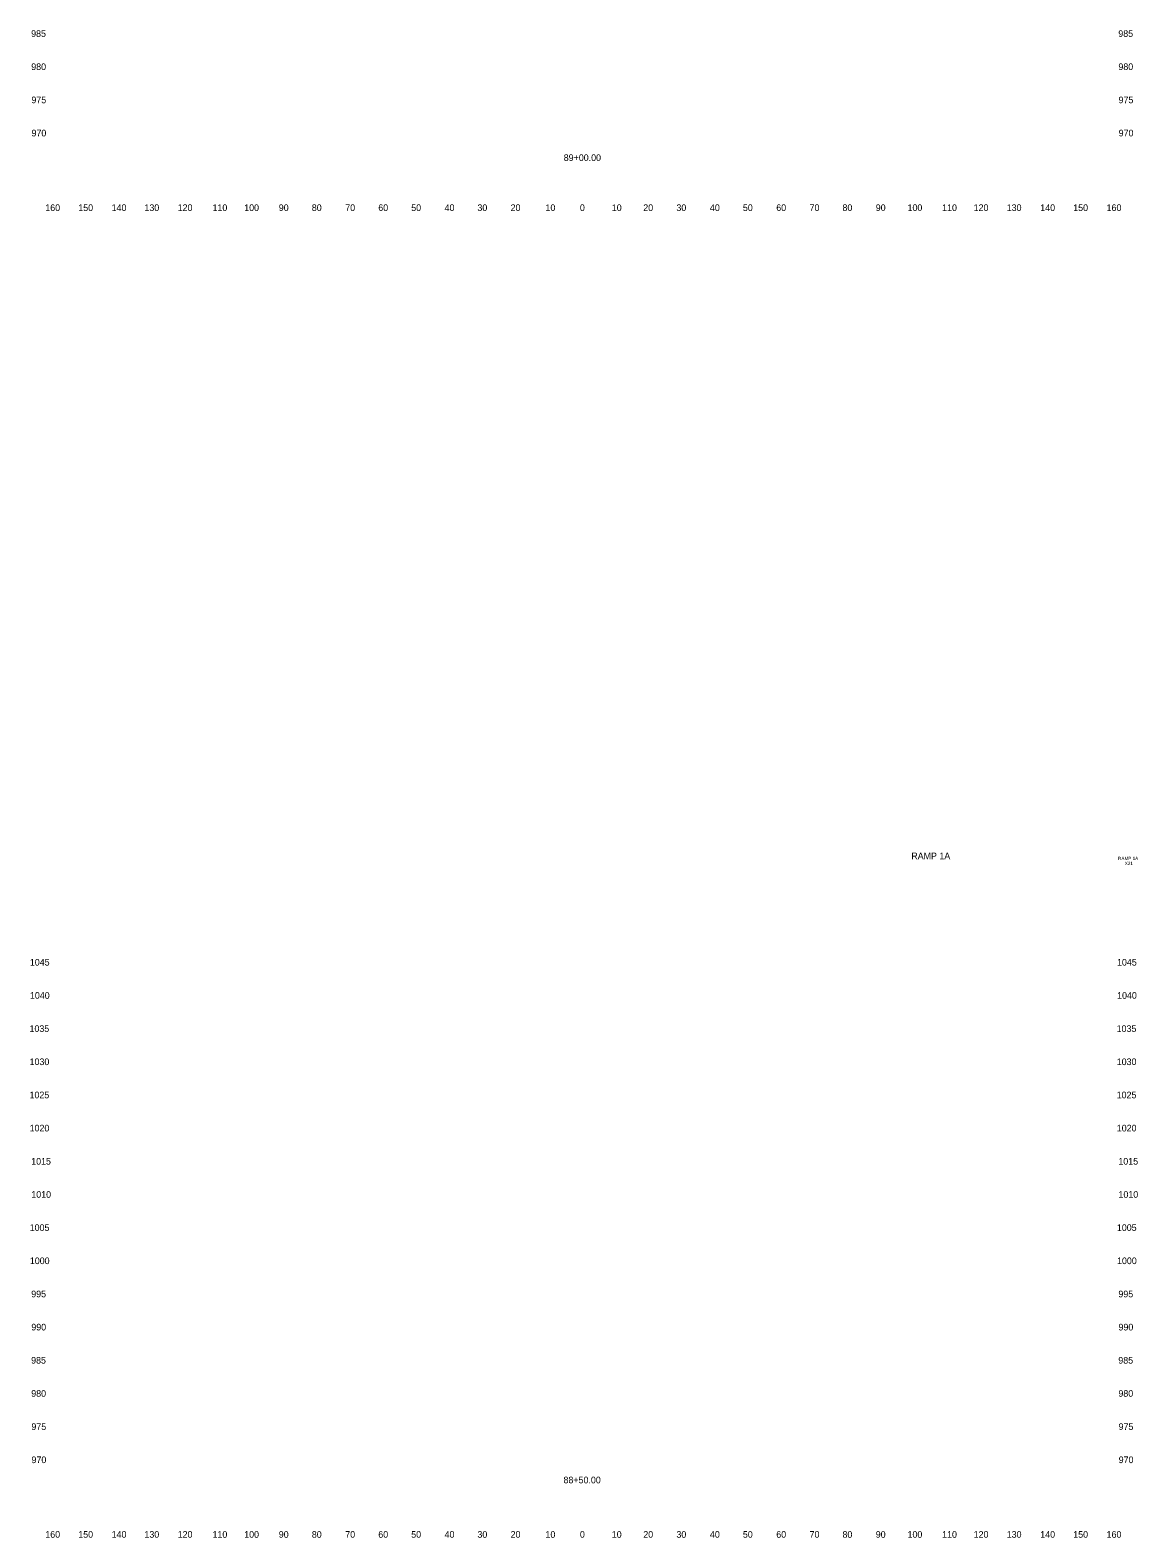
# Model space of a CAD drawing. Extents: x 4994 to 6873, y 4997 to 8804.
# Drawn here: x 6023.5 to 6357.5, y 4997.5 to 5452 of the extents above; entities that cross this region are included whole.
import ezdxf

# ---------------------------------------------------------------- set-up
doc = ezdxf.new("R2010")
doc.units = 0
for name, color, linetype in [('RD_SHT_ID', 7, 'Continuous'), ('RD_XS_TX_Offset', 7, 'Continuous'), ('RD_XS_TX_Station', 7, 'Continuous')]:
    doc.layers.add(name, color=color, linetype=linetype)

msp = doc.modelspace()

# ---------------------------------------------------------------- texts
at = {"layer": 'RD_SHT_ID'}
for s, height, p in [('RAMP 1A', 2, (6289.21, 5202.06)), ('RAMP 1A', 1, (6351.57, 5201.8)), ('X21', 1, (6353.57, 5200.3))]:
    msp.add_text(s, height=height, dxfattribs=at).set_placement(p)
at = {"layer": 'RD_XS_TX_Offset'}
for s, p in [('985', (6023.83, 5450)), ('985', (6351.63, 5450)), ('980', (6023.86, 5440)), ('980', (6351.66, 5440)), ('975', (6023.91, 5430)), ('975', (6351.71, 5430)), ('970', (6023.94, 5420)), ('970', (6351.74, 5420)), ('160', (6028.1, 5397.5)), ('150', (6038.04, 5397.5)), ('140', (6048.1, 5397.5)), ('130', (6057.99, 5397.5)), ('120', (6068.01, 5397.5)), ('110', (6078.51, 5397.5)), ('100', (6088.07, 5397.5)), ('90', (6098.5, 5397.5)), ('80', (6108.46, 5397.5)), ('70', (6118.54, 5397.5)), ('60', (6128.5, 5397.5)), ('50', (6138.43, 5397.5)), ('40', (6148.5, 5397.5)), ('30', (6158.39, 5397.5)), ('20', (6168.4, 5397.5)), ('10', (6178.91, 5397.5)), ('0', (6189.3, 5397.5)), ('0', (6189.3, 5397.5)), ('10', (6198.91, 5397.5)), ('20', (6208.4, 5397.5)), ('30', (6218.39, 5397.5)), ('40', (6228.5, 5397.5)), ('50', (6238.43, 5397.5)), ('60', (6248.5, 5397.5)), ('70', (6258.54, 5397.5)), ('80', (6268.46, 5397.5)), ('90', (6278.5, 5397.5)), ('100', (6288.07, 5397.5)), ('110', (6298.51, 5397.5)), ('120', (6308.01, 5397.5)), ('130', (6317.99, 5397.5)), ('140', (6328.1, 5397.5)), ('150', (6338.04, 5397.5)), ('160', (6348.1, 5397.5)), ('1045', (6023.44, 5170)), ('1045', (6351.24, 5170)), ('1040', (6023.47, 5160)), ('1040', (6351.27, 5160)), ('1035', (6023.33, 5150)), ('1035', (6351.13, 5150)), ('1030', (6023.36, 5140)), ('1030', (6351.16, 5140)), ('1025', (6023.34, 5130)), ('1025', (6351.14, 5130)), ('1020', (6023.37, 5120)), ('1020', (6351.17, 5120)), ('1015', (6023.85, 5110)), ('1015', (6351.65, 5110)), ('1010', (6023.88, 5100)), ('1010', (6351.68, 5100)), ('1005', (6023.4, 5090)), ('1005', (6351.2, 5090)), ('1000', (6023.44, 5080)), ('1000', (6351.24, 5080)), ('995', (6023.86, 5070)), ('995', (6351.66, 5070)), ('990', (6023.89, 5060)), ('990', (6351.69, 5060)), ('985', (6023.83, 5050)), ('985', (6351.63, 5050)), ('980', (6023.86, 5040)), ('980', (6351.66, 5040)), ('975', (6023.91, 5030)), ('975', (6351.71, 5030)), ('970', (6023.94, 5020)), ('970', (6351.74, 5020)), ('160', (6028.1, 4997.5)), ('150', (6038.04, 4997.5)), ('140', (6048.1, 4997.5)), ('130', (6057.99, 4997.5)), ('120', (6068.01, 4997.5)), ('110', (6078.51, 4997.5)), ('100', (6088.07, 4997.5)), ('90', (6098.5, 4997.5)), ('80', (6108.46, 4997.5)), ('70', (6118.54, 4997.5)), ('60', (6128.5, 4997.5)), ('50', (6138.43, 4997.5)), ('40', (6148.5, 4997.5)), ('30', (6158.39, 4997.5)), ('20', (6168.4, 4997.5)), ('10', (6178.91, 4997.5)), ('0', (6189.3, 4997.5)), ('0', (6189.3, 4997.5)), ('10', (6198.91, 4997.5)), ('20', (6208.4, 4997.5)), ('30', (6218.39, 4997.5)), ('40', (6228.5, 4997.5)), ('50', (6238.43, 4997.5)), ('60', (6248.5, 4997.5)), ('70', (6258.54, 4997.5)), ('80', (6268.46, 4997.5)), ('90', (6278.5, 4997.5)), ('100', (6288.07, 4997.5)), ('110', (6298.51, 4997.5)), ('120', (6308.01, 4997.5)), ('130', (6317.99, 4997.5)), ('140', (6328.1, 4997.5)), ('150', (6338.04, 4997.5)), ('160', (6348.1, 4997.5))]:
    msp.add_text(s, height=2, dxfattribs=at).set_placement(p)
at = {"layer": 'RD_XS_TX_Station'}
for s, p in [('89+00.00', (6184.42, 5412.58)), ('88+50.00', (6184.35, 5013.92))]:
    msp.add_text(s, height=2, dxfattribs=at).set_placement(p)

doc.saveas('drawing.dxf')
